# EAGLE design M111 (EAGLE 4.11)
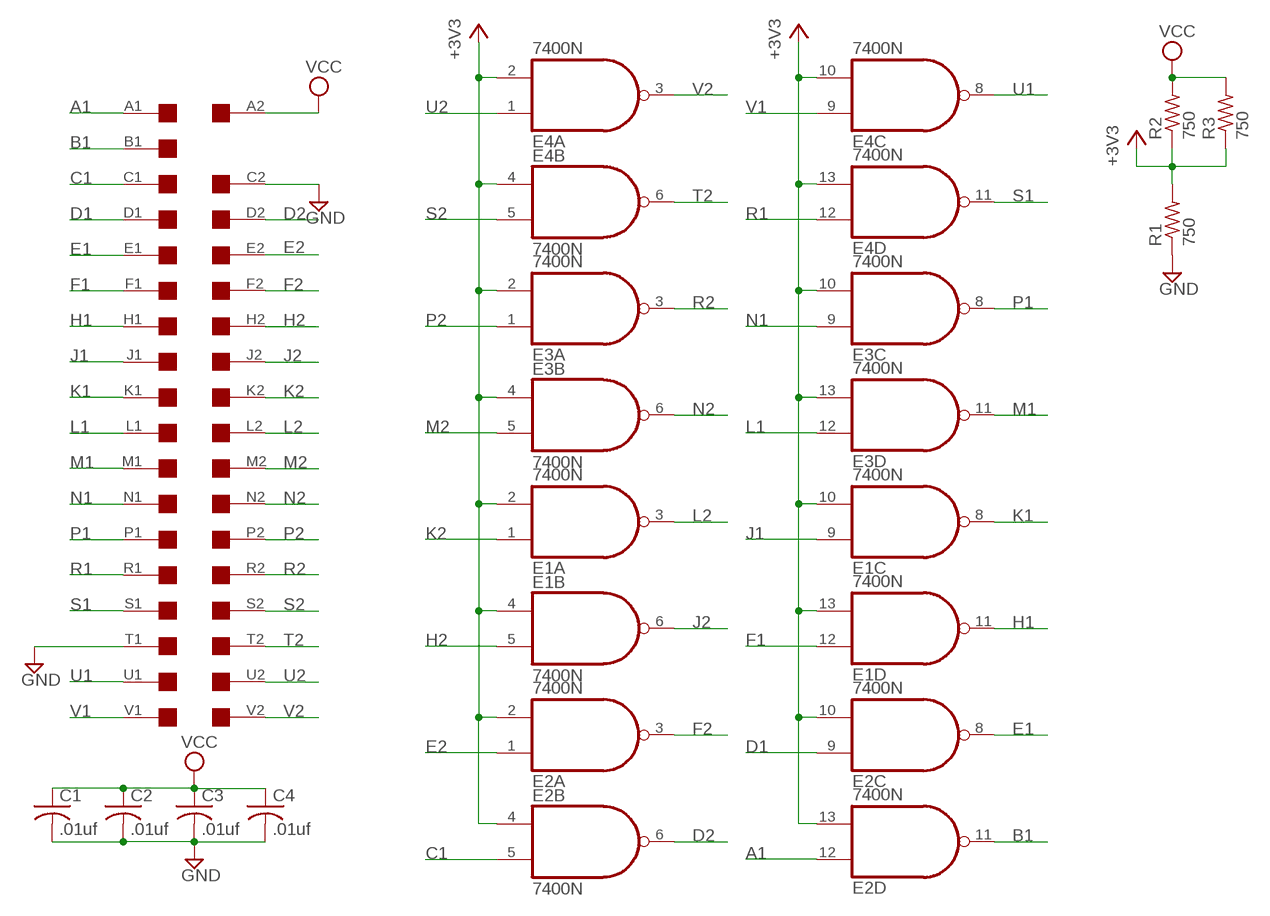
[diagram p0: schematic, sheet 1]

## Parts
A  EDGE-2  [EDGE-CON2]
C1  .01uf  C-US050-025X075  [C050-025X075]
C2  .01uf  C-US050-025X075  [C050-025X075]
C3  .01uf  C-US050-025X075  [C050-025X075]
C4  .01uf  C-US050-025X075  [C050-025X075]
E1  7400N  [DIL14]
E2  7400N  [DIL14]
E3  7400N  [DIL14]
E4  7400N  [DIL14]
R1  750  R-US_0207/10  [0207/10]
R2  750  R-US_0207/10  [0207/10]
R3  750  R-US_0207/10  [0207/10]

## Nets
+3V3: E1.2(A:I1) E1.4(B:I0) E1.10(C:I1) E1.13(D:I1) E2.2(A:I1) E2.4(B:I0) E2.10(C:I1) E2.13(D:I1) E3.2(A:I1) E3.4(B:I0) E3.10(C:I1) E3.13(D:I1) E4.2(A:I1) E4.4(B:I0) E4.10(C:I1) E4.13(D:I1) R1.2 R2.1 R3.1
A1: A.A1 E2.12(D:I0)
B1: A.B1 E2.11(D:O)
C1: A.C1 E2.5(B:I1)
D1: A.D1 E2.9(C:I0)
D2: A.D2 E2.6(B:O)
E1: A.E1 E2.8(C:O)
E2: A.E2 E2.1(A:I0)
F1: A.F1 E1.12(D:I0)
F2: A.F2 E2.3(A:O)
GND: A.C2 A.T1 C1.2 C2.2 C3.2 C4.2 R1.1
H1: A.H1 E1.11(D:O)
H2: A.H2 E1.5(B:I1)
J1: A.J1 E1.9(C:I0)
J2: A.J2 E1.6(B:O)
K1: A.K1 E1.8(C:O)
K2: A.K2 E1.1(A:I0)
L1: A.L1 E3.12(D:I0)
L2: A.L2 E1.3(A:O)
M1: A.M1 E3.11(D:O)
M2: A.M2 E3.5(B:I1)
N1: A.N1 E3.9(C:I0)
N2: A.N2 E3.6(B:O)
P1: A.P1 E3.8(C:O)
P2: A.P2 E3.1(A:I0)
R1: A.R1 E4.12(D:I0)
R2: A.R2 E3.3(A:O)
S1: A.S1 E4.11(D:O)
S2: A.S2 E4.5(B:I1)
T2: A.T2 E4.6(B:O)
U1: A.U1 E4.8(C:O)
U2: A.U2 E4.1(A:I0)
V1: A.V1 E4.9(C:I0)
V2: A.V2 E4.3(A:O)
VCC: A.A2 C1.1 C2.1 C3.1 C4.1 R2.2 R3.2
Unconnected: A.B2

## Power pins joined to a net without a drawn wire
GND: E1.7(P:GND) E2.7(P:GND) E3.7(P:GND) E4.7(P:GND)
VCC: E1.14(P:VCC) E2.14(P:VCC) E3.14(P:VCC) E4.14(P:VCC)

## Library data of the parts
A = dec-con:EDGE-2: Double-Sided DEC edge connector.
C1-C4 = rcl:C-US: CAPACITOR, American symbol
E1-E4 = 74xx-us:74*00: Quad 2-input NAND gate
R1-R3 = rcl:R-US_: RESISTOR, American symbol

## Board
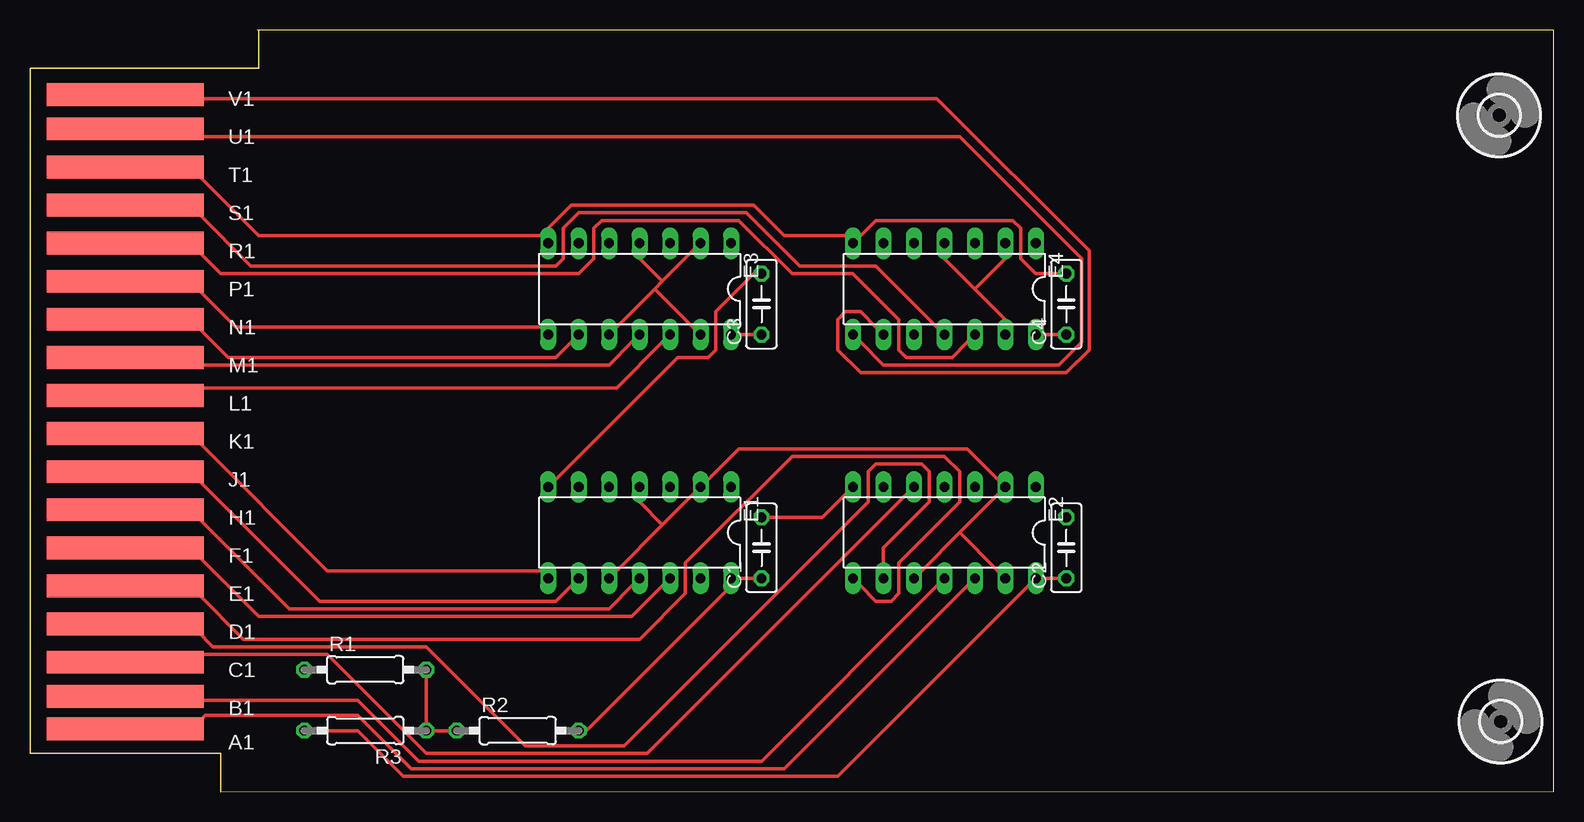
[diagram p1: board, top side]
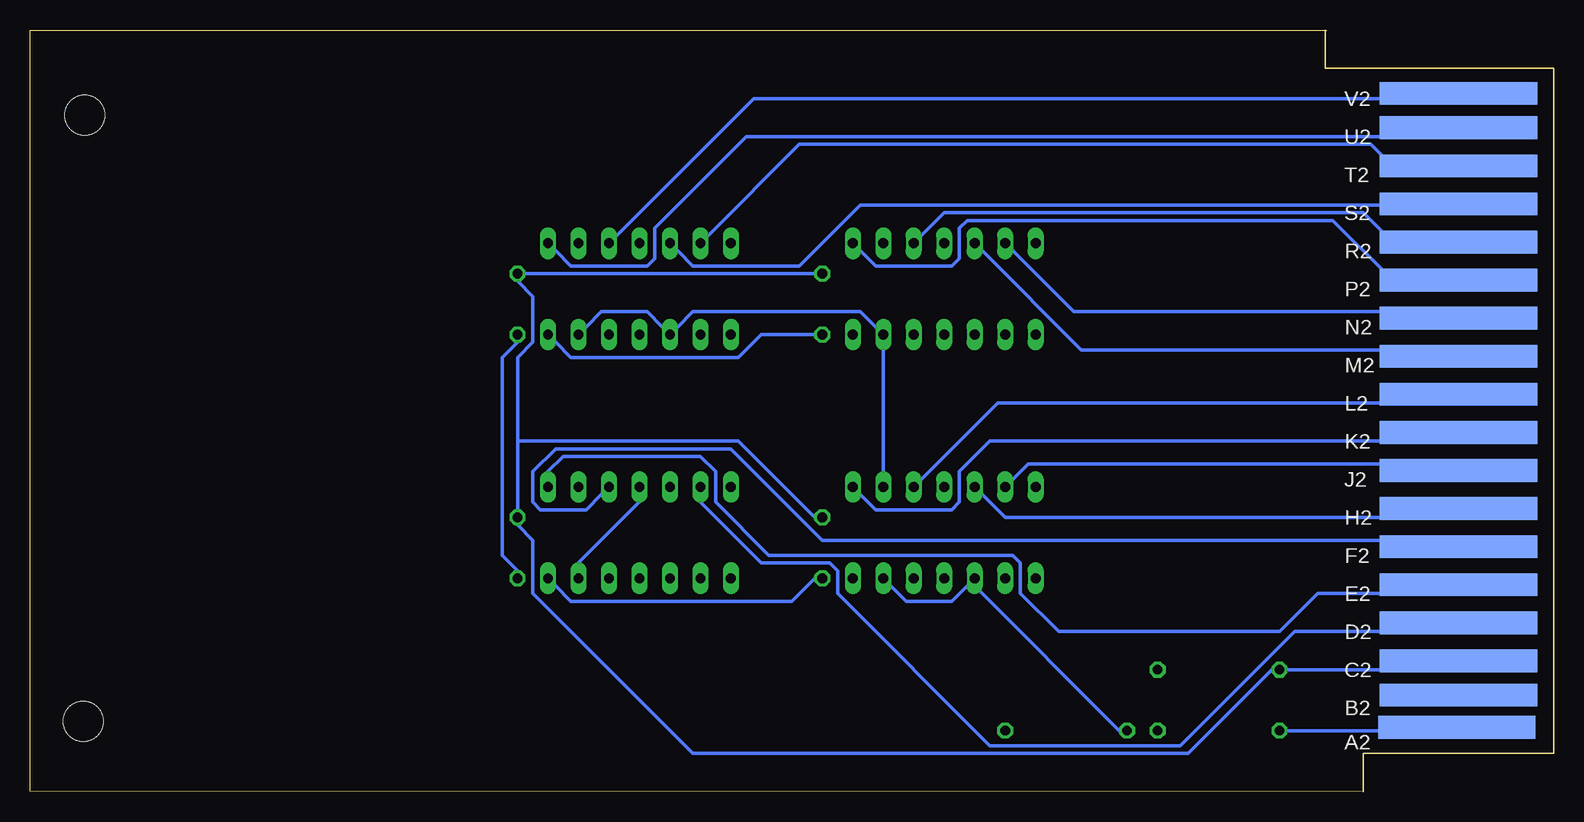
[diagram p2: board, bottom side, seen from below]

Size 126.98 x 63.5 mm. Coordinates in mm from the lower left corner, seen from the top.
Outline: 15.88,0 126.98,0.04 126.98,63.46 18.92,63.5
Copper layers (1*16): Top 0.035mm / dielectric 1.5mm / Bottom 0.035mm
Design rules "10mils": minimum track width 12mil, minimum drill 28mil, track to track 10mil, track to pad 10mil, pad to pad 10mil, via to via 10mil, smd to smd 10mil, copper to edge 40mil, drill to drill 10mil, minimum pad ring 10mil, minimum via ring 8mil, stop-mask expansion 0mil, vias tented up to drill 0mil, thermal gap 10mil

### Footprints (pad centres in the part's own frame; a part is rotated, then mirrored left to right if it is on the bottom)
EDGE-CON2 = smd 13.106 x 1.905: A1 7.938,5.239; B1 7.938,7.938; C1 7.938,10.795; D1 7.938,13.97; E1 7.938,17.145; F1 7.938,20.32; H1 7.938,23.495; J1 7.938,26.67; K1 7.938,29.845; L1 7.938,33.02; M1 7.938,36.195; N1 7.938,39.37; P1 7.938,42.545; R1 7.938,45.72; S1 7.938,48.895; T1 7.938,52.07; U1 7.938,55.245; V1 7.938,58.102 | smd 13.106 x 1.905 bottom: A2 8.096,5.34; B2 7.938,8.039; C2 7.938,10.897; D2 7.938,14.072; E2 7.938,17.247; F2 7.938,20.422; H2 7.938,23.597; J2 7.938,26.772; K2 7.938,29.947; L2 7.938,33.122; M2 7.938,36.297; N2 7.938,39.472; P2 7.938,42.647; R2 7.938,45.822; S2 7.938,48.997; T2 7.938,52.172; U2 7.938,55.347; V2 7.938,58.204
C050-025X075 = drill 0.813 octagon: 1 -2.54,0; 2 2.54,0
DIL14 = drill 0.813 long: 1 -7.62,-3.81; 2 -5.08,-3.81; 3 -2.54,-3.81; 4 0,-3.81; 5 2.54,-3.81; 6 5.08,-3.81; 7 7.62,-3.81; 8 7.62,3.81; 9 5.08,3.81; 10 2.54,3.81; 11 0,3.81; 12 -2.54,3.81; 13 -5.08,3.81; 14 -7.62,3.81
0207/10 = drill 0.813 octagon: 1 -5.08,0; 2 5.08,0
3,3 = hole 3.3: 0,0

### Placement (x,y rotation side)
A  0,0 0 top
C1  60.96,20.32 90 top
C2  86.36,20.32 90 top
C3  60.96,40.64 90 top
C4  86.36,40.64 90 top
E1  50.8,21.59 180 top
E2  76.2,21.59 180 top
E3  50.8,41.91 180 top
E4  76.2,41.91 180 top
R1  27.94,10.16 0 top
R2  40.64,5.08 0 top
R3  27.94,5.08 180 top
U$2  [3,3]  122.43,56.39 0 top
U$3  [3,3]  122.56,5.84 0 top

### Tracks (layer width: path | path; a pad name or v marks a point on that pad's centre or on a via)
+3V3
  Top 0.305: 78.74,41.91 81.28,39.37 E4.13 | 78.74,41.91 76.2,44.45 E4.4 | 78.74,41.91 81.28,44.45 E4.2 | 52.7,42.55 55.24,45.09 E3.2 | 52.07,41.91 52.7,42.55 | 52.07,41.91 48.9,38.73 E3.10 | 52.7,42.55 50.8,44.45 E3.4 | 52.07,41.91 55.24,38.73 E3.13 | 77.47,21.59 80.64,24.77 E2.2 80.64,26.04 78.11,28.57 59.05,28.57 56.52,26.04 E1.2 55.24,24.77 52.7,22.23 | 77.47,21.59 74.3,18.41 E2.10 | 77.47,21.59 80.64,18.41 E2.13 | R2.1 34.92,5.08 33.66,5.08 R3.1 33.02,5.71 33.02,9.53 R1.2 | 52.7,22.23 48.9,18.41 E1.10 | 52.7,22.23 50.8,24.13 E1.4
  Bottom 0.305: E4.13 80.64,38.73 79.38,40.01 75.56,40.01 74.3,38.73 E4.10 73.03,38.73 71.75,40.01 57.78,40.01 56.52,38.73 E3.13 55.88,36.83 55.88,26.67 E1.2 | E2.4 76.2,24.13 81.28,19.05 E2.13 | E1.13 55.24,17.14 53.98,15.88 50.16,15.88 48.9,17.14 E1.10 48.26,17.14 36.2,5.08 R2.1
A1
  Top 0.305: E2.12 78.11,17.14 62.87,1.91 31.75,1.91 27.3,6.35 14.61,6.35 13.97,5.71 A.A1
B1
  Top 0.305: E2.11 75.56,17.14 60.96,2.54 32.38,2.54 27.3,7.62 13.97,7.62 A.B1
C1
  Top 0.305: E2.5 73.03,24.77 51.44,3.17 33.02,3.17 24.77,11.43 13.97,11.43 A.C1
D1
  Top 0.305: E2.9 71.12,19.05 71.12,20.32 74.93,24.13 74.93,26.67 74.3,27.3 70.48,27.3 69.85,26.67 69.85,24.13 49.53,3.81 41.27,3.81 33.02,12.06 15.24,12.06 13.97,13.34 A.D1
D2
  Bottom 0.305: E2.6 71.12,24.13 66.04,19.05 60.33,19.05 59.69,18.41 59.69,16.51 46.99,3.81 31.11,3.81 21.59,13.34 13.97,13.34 A.D2
E1
  Top 0.305: E2.8 69.22,17.14 70.48,15.88 71.75,15.88 72.39,16.51 72.39,19.05 77.47,24.13 77.47,26.67 76.2,27.94 63.5,27.94 54.61,19.05 54.61,16.51 50.8,12.7 17.78,12.7 13.97,16.51 A.E1
E2
  Bottom 0.305: E2.1 83.82,26.67 82.55,27.94 71.12,27.94 69.85,26.67 69.85,24.13 65.41,19.68 45.09,19.68 44.45,19.05 44.45,16.51 41.27,13.34 22.86,13.34 19.68,16.51 13.97,16.51 A.E2
F1
  Top 0.305: E1.12 52.7,17.14 50.16,14.61 19.05,14.61 13.97,19.68 A.F1
F2
  Bottom 0.305: E2.3 79.38,24.77 80.64,23.5 84.45,23.5 85.09,24.13 85.09,26.67 83.19,28.57 68.58,28.57 60.96,20.95 13.97,20.95 A.F2
GND
  Top 0.305: A.T1 13.97,51.44 19.05,46.35 42.55,46.35 E3.7 43.18,46.99 45.09,48.9 60.33,48.9 62.87,46.35 67.94,46.35 E4.7 69.22,46.35 70.48,47.62 81.92,47.62 82.55,46.99 82.55,44.45 83.82,43.18 85.72,43.18 C4.2 | E1.7 43.81,26.04 53.98,36.2 56.52,36.2 57.15,36.83 57.15,40.01 60.33,43.18 C3.2 | C1.2 61.59,22.86 66.04,22.86 67.94,24.77 E2.7
  Bottom 0.305: A.C2 13.97,10.16 22.23,10.16 R1.1 23.5,10.16 30.48,3.17 71.75,3.17 85.09,16.51 85.09,20.95 86.36,22.23 C2.2 86.36,23.5 86.36,29.21 | 86.36,29.21 86.36,36.2 85.09,37.47 85.09,41.27 86.36,42.55 C4.2 85.72,43.18 61.59,43.18 C3.2 | 86.36,29.21 67.94,29.21 61.59,22.86 C1.2
H1
  Top 0.305: E1.11 50.16,17.14 48.26,15.24 21.59,15.24 13.97,22.86 A.H1
H2
  Bottom 0.305: E1.5 47.62,24.77 45.72,22.86 13.97,22.86 A.H2
J1
  Top 0.305: E1.9 45.09,17.14 43.81,15.88 24.13,15.88 13.97,26.04 A.J1
J2
  Bottom 0.305: E1.6 45.09,26.04 43.81,27.3 13.97,27.3 A.J2
K1
  Top 0.305: E1.8 42.55,18.41 24.77,18.41 13.97,29.21 A.K1
K2
  Bottom 0.305: E1.1 57.78,24.77 56.52,23.5 50.16,23.5 49.53,24.13 49.53,26.67 46.99,29.21 13.97,29.21 A.K2
L1
  Top 0.305: E3.12 52.7,37.47 48.9,33.66 13.97,33.66 A.L1
L2
  Bottom 0.305: E1.3 52.7,26.04 46.35,32.38 13.97,32.38 A.L2
M1
  Top 0.305: E3.11 50.16,37.47 48.26,35.56 13.97,35.56 A.M1
M2
  Bottom 0.305: E3.5 47.62,45.09 39.37,36.83 13.97,36.83 A.M2
N1
  Top 0.305: E3.9 45.09,37.47 43.81,36.2 16.51,36.2 13.97,38.73 A.N1
N2
  Bottom 0.305: E3.6 45.09,45.09 40.01,40.01 13.97,40.01 A.N2
P1
  Top 0.305: E3.8 42.55,38.73 17.14,38.73 13.97,41.91 A.P1
P2
  Bottom 0.305: E3.1 57.78,45.09 56.52,43.81 50.16,43.81 49.53,44.45 49.53,46.99 48.9,47.62 18.41,47.62 13.97,43.18 A.P2
R1
  Top 0.305: E4.12 78.11,37.47 76.83,36.2 73.03,36.2 72.39,36.83 72.39,39.37 68.58,43.18 63.5,43.18 59.05,47.62 47.62,47.62 46.99,46.99 46.99,44.45 45.72,43.18 15.88,43.18 13.97,45.09 A.R1
R2
  Bottom 0.305: E3.3 52.7,46.35 50.8,48.26 15.88,48.26 13.97,46.35 A.R2
S1
  Top 0.305: E4.11 75.56,38.73 70.48,43.81 64.14,43.81 59.69,48.26 45.72,48.26 44.45,46.99 44.45,44.45 43.81,43.81 18.41,43.81 13.97,48.26 A.S1
S2
  Bottom 0.305: E4.5 73.03,45.09 71.75,43.81 62.87,43.81 57.78,48.9 13.97,48.9 A.S2
T2
  Bottom 0.305: E4.6 70.48,46.35 62.87,53.98 15.24,53.98 13.97,52.7 A.T2
U1
  Top 0.305: E4.8 69.22,37.47 71.12,35.56 85.72,35.56 87.63,37.47 87.63,44.45 77.47,54.61 13.97,54.61 A.U1
U2
  Bottom 0.305: E4.1 83.19,45.09 81.92,43.81 75.56,43.81 74.93,44.45 74.93,46.99 67.31,54.61 13.97,54.61 A.U2
V1
  Top 0.305: E4.9 70.48,38.73 69.22,40.01 67.94,40.01 67.31,39.37 67.31,36.83 69.22,34.92 86.36,34.92 88.27,36.83 88.27,45.09 75.56,57.78 13.97,57.78 A.V1
V2
  Bottom 0.305: E4.3 78.11,46.35 66.67,57.78 13.97,57.78 A.V2
VCC
  Top 0.305: E3.14 59.05,38.1 60.33,38.1 C3.1 | E4.14 84.45,38.1 85.72,38.1 C4.1 | C2.1 85.72,17.78 84.45,17.78 E2.14 83.19,17.14 67.31,1.27 31.11,1.27 27.3,5.08 23.5,5.08 R3.2 | R2.2 46.35,5.08 58.42,17.14 E1.14 59.05,17.78 60.33,17.78 C1.1
  Bottom 0.305: R3.2 22.23,5.08 14.61,5.08 A.A2 | C3.1 61.59,38.1 66.04,38.1 67.94,36.2 81.92,36.2 83.19,37.47 E4.14 | E2.14 83.19,17.14 81.92,15.88 63.5,15.88 61.59,17.78 C1.1 | C4.1 86.36,37.47 87.63,36.2 87.63,19.68 86.36,18.41 C2.1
